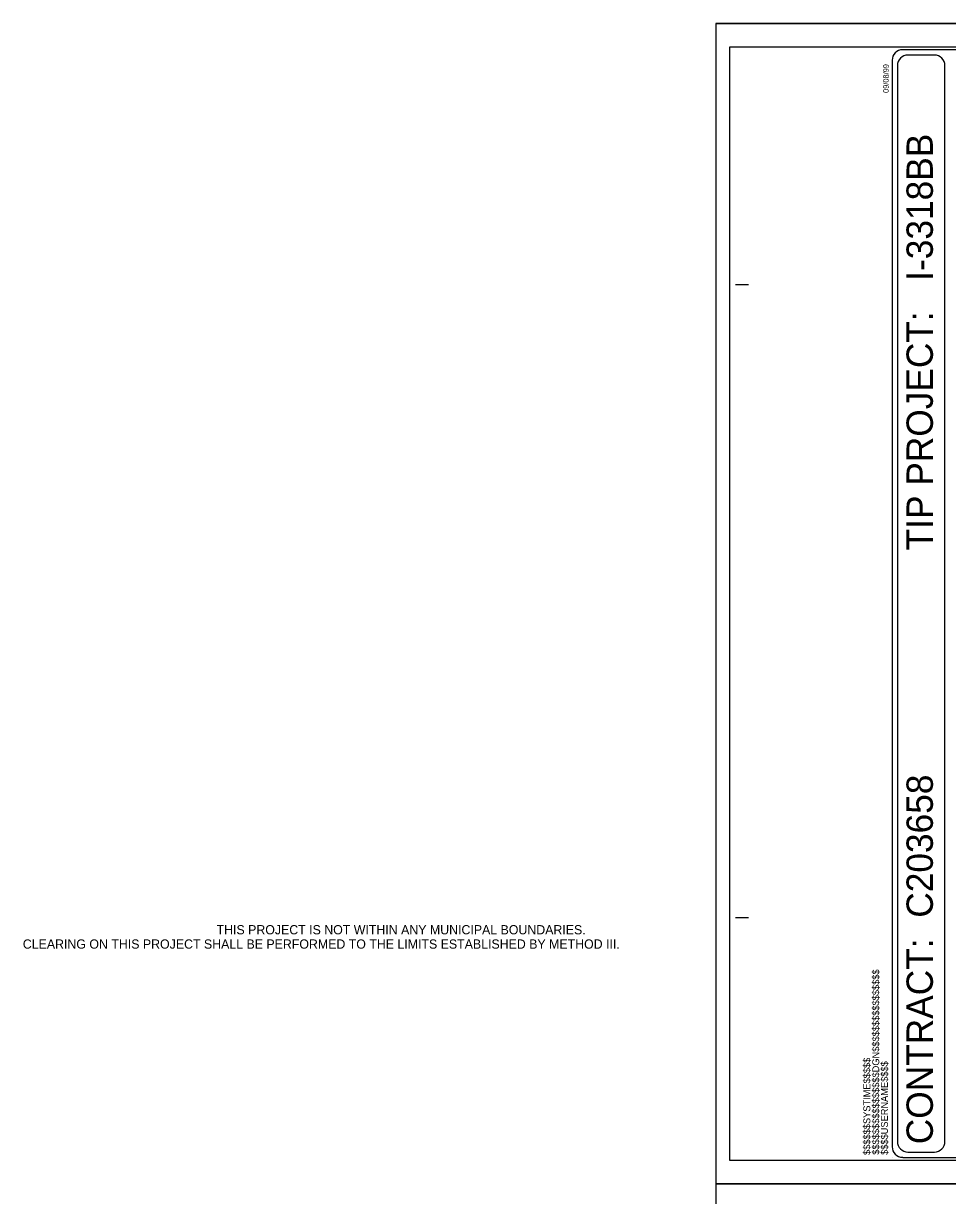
# Model space of a CAD drawing. Extents: x 2241278 to 2254132, y 649924 to 670434.
# Drawn here: x 2241278 to 2245656, y 660843 to 666399 of the extents above; entities that cross this region are included whole.
import ezdxf

# ---------------------------------------------------------------- set-up
doc = ezdxf.new("R2010")
doc.units = 0
for name, color, linetype in [('Prop RDY Alternate Text Yellow', 7, 'Continuous'), ('Sheet Block Title CELL', 7, 'Continuous'), ('Sheet Cutting Line CELL', 7, 'Continuous'), ('Sheet Data Field CELL', 7, 'Continuous'), ('Sheet Plot Border Inside CELL', 7, 'Continuous'), ('Sheet Plot Border Outside CELL', 7, 'Continuous'), ('Sheet Title CELL', 7, 'Continuous')]:
    doc.layers.add(name, color=color, linetype=linetype)

msp = doc.modelspace()

# ---------------------------------------------------------------- linework, layer by layer
at = {"layer": 'Sheet Cutting Line CELL'}
for p, q in [((2244558.8, 666399.1), (2252978.8, 666399.1)), ((2244558.8, 666399.1), (2244558.8, 660899.2)), ((2244558.8, 660899.2), (2252978.8, 660899.2)), ((2252978.8, 660899.2), (2244558.8, 660899.2)), ((2244558.8, 660899.2), (2244558.8, 655399.2))]:
    msp.add_line(p, q, dxfattribs=at)
at = {"layer": 'Sheet Data Field CELL'}
msp.add_line((2245393.8, 661024.2), (2245393.8, 661024.2), dxfattribs=at)
at = {"layer": 'Sheet Plot Border Inside CELL'}
msp.add_lwpolyline([(2244623.8, 661011.4), (2252956.3, 661011.4), (2252956.3, 666286.9), (2244623.8, 666286.9)], close=True, dxfattribs=at)
at = {"layer": 'Sheet Plot Border Outside CELL'}
for points in [[(2252978.8, 666399.1), (2244558.8, 666399.1), (2244558.8, 660899.2), (2252978.8, 660899.2)], [(2244558.8, 655399.2), (2252978.8, 655399.2), (2252978.8, 660899.2), (2244558.8, 660899.2)]]:
    msp.add_lwpolyline(points, close=True, dxfattribs=at)
at = {"layer": 'Sheet Title CELL'}
for p, q in [((2245643.8, 661099.2), (2245643.8, 666199.2)), ((2244651.3, 665161.6), (2244713.8, 665161.6)), ((2244651.3, 665161.6), (2244713.8, 665161.6)), ((2244651.3, 662161.6), (2244713.8, 662161.7)), ((2244651.3, 662161.6), (2244713.8, 662161.7)), ((2245393.8, 661024.2), (2245393.8, 661024.2)), ((2245393.8, 661024.2), (2245393.8, 661024.2)), ((2245393.8, 661024.2), (2245393.8, 661024.2)), ((2245393.8, 661024.2), (2245393.8, 661024.2))]:
    msp.add_line(p, q, dxfattribs=at)
for points in [[(2252843.8, 666274.1), (2245443.7, 666274.2)], [(2245593.8, 666249.1), (2245468.8, 666249.2)], [(2245393.8, 666224.2), (2245393.8, 661074.2)], [(2245393.8, 666224.2), (2245393.8, 661074.2)], [(2245418.8, 666199.2), (2245418.8, 661099.2)], [(2245443.8, 661024.1), (2252843.8, 661024.1)], [(2245468.7, 661049.2), (2245593.8, 661049.2)]]:
    msp.add_lwpolyline(points, dxfattribs=at)
for centre, start, end in [((2245443.8, 666224.4), 90, 180), ((2245468.8, 666199.4), 90, 180), ((2245593.8, 666199.4), 0, 90), ((2245443.8, 661074.4), 180, 270), ((2245468.8, 661099.4), 180, 270), ((2245593.8, 661099.4), 270, 360)]:
    msp.add_arc(centre, 50, start, end, dxfattribs=at)

# ---------------------------------------------------------------- texts
at = {"layer": 'Prop RDY Alternate Text Yellow'}
msp.add_text('CLEARING ON THIS PROJECT SHALL BE PERFORMED TO THE LIMITS ESTABLISHED BY METHOD III.', height=43.751, dxfattribs=at).set_placement((2241275.1, 662013.4))
at = {"layer": 'Sheet Block Title CELL'}
msp.add_text('THIS PROJECT IS NOT WITHIN ANY MUNICIPAL BOUNDARIES.', height=43.751, dxfattribs=at).set_placement((2242193, 662081.2))
at = {"layer": 'Sheet Title CELL'}
for s, height, p in [('09/08/99', 26.25, (2245377.5, 666069.8)), ('I-3318BB', 125, (2245586.8, 665179.4)), ('TIP PROJECT:', 125, (2245586.8, 663901.6)), ('C203658', 125, (2245586.8, 662160.1)), ('CONTRACT:', 125, (2245586.8, 661086.5)), ('$$$$$$$$$$$$$$$$DGN$$$$$$$$$$$$$$$$', 32.812, (2245332.7, 661036.7)), ('$$$$$$SYSTIME$$$$$', 32.812, (2245290.2, 661035.5)), ('$$$$USERNAME$$$$', 32.812, (2245373.7, 661035.9))]:
    msp.add_text(s, height=height, rotation=90, dxfattribs=at).set_placement(p)

doc.saveas('drawing.dxf')
